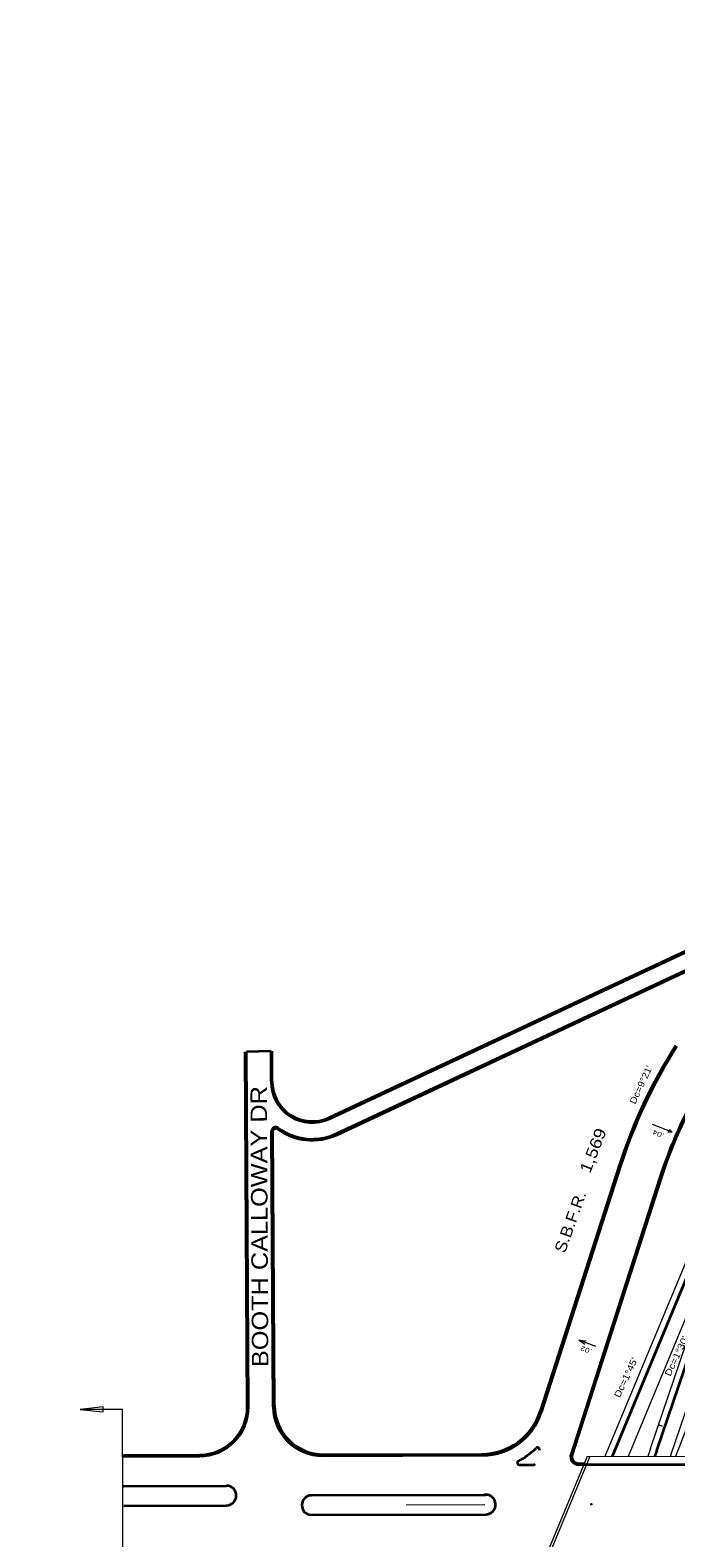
# Model space of a CAD drawing. Extents: x 2354993 to 2372084, y 6966390 to 6990057.
# Drawn here: x 2364099 to 2364884, y 6980481 to 6982315 of the extents above; entities that cross this region are included whole.
import ezdxf
from ezdxf.enums import TextEntityAlignment as Align

# ---------------------------------------------------------------- set-up
doc = ezdxf.new("R2010")
doc.units = 0
doc.header["$LTSCALE"] = 3.2
doc.header["$PDMODE"] = 32
doc.header["$PDSIZE"] = 1.6
for name, color, linetype, lineweight in [('1', 7, 'Continuous', 13), ('13', 7, 'Continuous', 13), ('15', 7, 'Continuous', 13), ('17', 7, 'Continuous', 13), ('19', 7, 'Continuous', 13), ('2', 7, 'Continuous', 35), ('4', 7, 'Continuous', 13), ('5', 7, 'Continuous', 35), ('8', 7, 'Continuous', 13), ('9', 7, 'Continuous', 13)]:
    doc.layers.add(name, color=color, linetype=linetype, lineweight=lineweight)

msp = doc.modelspace()

# ---------------------------------------------------------------- linework, layer by layer
at = {"layer": '1'}
for q in [(2364856.139, 6980983.553), (2364874.732, 6980974.05), (2364876.587, 6980977.317)]:
    msp.add_line((2364879.743, 6980974.088), q, dxfattribs=at)
at = {"layer": '15'}
msp.add_lwpolyline([(2364212.059, 6980404.032), (2364211.303, 6980637.104), (2364159.893, 6980636.937), (2364187.903, 6980634.029), (2364187.883, 6980640.028), (2364159.893, 6980636.937)], dxfattribs=at)
at = {"layer": '19'}
for p, q in [((2364766.943, 6980721.165), (2364773.594, 6980716.189)), ((2364766.943, 6980721.165), (2364775.222, 6980720.439)), ((2364786.963, 6980713.517), (2364766.943, 6980721.165))]:
    msp.add_line(p, q, dxfattribs=at)
at = {"layer": '2'}
for p, q in [((2364391.894, 6981072.689), (2364362.145, 6981071.936)), ((2364995.931, 6981035.023), (2364806.866, 6980579.777)), ((2364861.207, 6980586.955), (2365010.841, 6981027.825)), ((2364815.569, 6980933.575), (2364719.53, 6980634.813)), ((2364816.997, 6980933.115), (2364720.623, 6980633.313)), ((2364864.598, 6980917.813), (2364756.875, 6980582.707)), ((2364866.026, 6980917.355), (2364757.927, 6980581.077)), ((2364766.423, 6980571.147), (2364773.035, 6980571.167)), ((2364766.428, 6980569.647), (2365268.294, 6980571.275))]:
    msp.add_line(p, q, dxfattribs=at)
at = {"layer": '2', "lineweight": 13}
msp.add_line((2364868.163, 6980616.404), (2364863.537, 6980618.306), dxfattribs=at)
at = {"layer": '2'}
for centre, radius, start, end in [((2365412.01, 6980741.844), 575, 137.55934, 162.17959), ((2365412.01, 6980741.844), 573.5, 137.55934, 162.17959), ((2365412.01, 6980741.844), 626.5, 147.37736, 162.17959), ((2365412.01, 6980741.844), 625, 147.37736, 162.17959), ((2364766.395, 6980579.646), 10, 162.1796, 270.18593), ((2364766.395, 6980579.646), 8.5, 162.1796, 270.18593), ((2370300.051, 6978740.971), 5743.578, 161.2524, 161.32623)]:
    msp.add_arc(centre, radius, start, end, dxfattribs=at)
at = {"layer": '4'}
for p, q in [((2364988.543, 6981038.091), (2364798.192, 6980579.749)), ((2364878.249, 6980581.158), (2365013.559, 6980979.825)), ((2364911.473, 6980784.729), (2364826.382, 6980579.841)), ((2364853.631, 6980589.527), (2364918.845, 6980781.667)), ((2364884.273, 6980580.029), (2364899.617, 6980619.817))]:
    msp.add_line(p, q, dxfattribs=at)
for centre, radius, start, end in [((2370300.051, 6978740.971), 5751.578, 161.2524, 161.35344), ((2370300.048, 6978740.957), 5725.578, 161.25239, 161.26454)]:
    msp.add_arc(centre, radius, start, end, dxfattribs=at)
at = {"layer": '5'}
for p, q in [((2364462.463, 6980991.963), (2365011.662, 6981248.793)), ((2364463.098, 6980990.605), (2365012.297, 6981247.435)), ((2364471.57, 6980972.489), (2364995.066, 6981217.297)), ((2364472.205, 6980971.129), (2364995.702, 6981215.939)), ((2364363.031, 6980640.465), (2364360.645, 6981071.95)), ((2364364.531, 6980640.473), (2364362.145, 6981071.936)), ((2364391.918, 6981035.865), (2364391.894, 6981072.689)), ((2364393.418, 6981035.867), (2364393.394, 6981072.689)), ((2364394.533, 6980640.301), (2364392.68, 6980975.305)), ((2364396.024, 6980641.812), (2364394.18, 6980975.315)), ((2364212.213, 6980579.839), (2364304.727, 6980580.141)), ((2364212.519, 6980581.341), (2364304.723, 6980581.641)), ((2364454.727, 6980580.633), (2364649.465, 6980581.266)), ((2364456.218, 6980582.144), (2364648.372, 6980582.766)), ((2364694.002, 6980569.411), (2364711.252, 6980569.466)), ((2364212.641, 6980543.847), (2364337.806, 6980544.253)), ((2364440.321, 6980532.586), (2364653.411, 6980533.278)), ((2364212.718, 6980519.849), (2364337.882, 6980520.255)), ((2364440.125, 6980508.585), (2364653.513, 6980509.278))]:
    msp.add_line(p, q, dxfattribs=at)
at = {"layer": '5', "lineweight": 13}
for p, q in [((2364776.569, 6980579.679), (2364728.333, 6980463.531)), ((2364779.822, 6980579.689), (2364731.586, 6980463.541)), ((2364776.569, 6980579.679), (2365273.39, 6980581.292)), ((2364766.425, 6980570.647), (2365268.291, 6980572.275))]:
    msp.add_line(p, q, dxfattribs=at)
at = {"layer": '5'}
for centre, radius, start, end in [((2364441.918, 6981035.898), 50, 180.03669, 295.06272), ((2364441.918, 6981035.898), 48.5, 180.03669, 295.06272), ((2364397.68, 6980975.334), 5, 53.85481, 180.31682), ((2364397.68, 6980975.333), 3.5, 53.85483, 180.31682), ((2364441.918, 6981035.898), 71.5, 233.85483, 295.06321), ((2364441.918, 6981035.898), 70, 233.85481, 295.06292), ((2364304.532, 6980640.141), 58.5, 270.18698, 0.31682), ((2364304.532, 6980640.141), 60, 270.18697, 0.31682), ((2364454.532, 6980640.633), 60, 180.31685, 270.18617), ((2364456.023, 6980642.143), 60, 180.31686, 270.18557), ((2364648.129, 6980657.766), 75, 270.1855, 342.17971), ((2364649.222, 6980656.265), 75, 270.18614, 342.1796), ((2364649.222, 6980656.265), 93, 297.95774, 314.40722), ((2364716.048, 6980588.042), 2.5, 342.18249, 134.40722), ((2364693.994, 6980571.911), 2.5, 117.95774, 270.18545), ((2364711.246, 6980571.466), 2, 270.18405, 342.18207), ((2364337.694, 6980532.254), 12, 270.89854, 89.46436), ((2364441.434, 6980520.513), 12, 94.01279, 263.73872), ((2364653.272, 6980521.276), 12, 271.15204, 102.25782)]:
    msp.add_arc(centre, radius, start, end, dxfattribs=at)
at = {"layer": '8'}
msp.add_line((2364556.228, 6980520.961), (2364652.074, 6980521.273), dxfattribs=at)
at = {"layer": '9'}
msp.add_arc((2360722.521, 6984327.136), 5729.573, 359.50797, 359.50797, dxfattribs=at)
msp.add_point((2364781.691, 6980521.694), dxfattribs=at)

# ---------------------------------------------------------------- texts
at = {"layer": '13', "width": 1.15}
msp.add_text('BOOTH CALLOWAY DR', height=20, rotation=90.317, dxfattribs=at).set_placement((2364387.791, 6980859.464), align=Align.CENTER)
at = {"layer": '13'}
for s, rotation, width, p in [('1,569', 68.675, 1.2, (2364779.967, 6980923.233)), ('S.B.F.R.', 70.193, 1.1, (2364749.474, 6980826.321))]:
    msp.add_text(s, height=14, rotation=rotation, dxfattribs=dict(at, width=width)).set_placement(p)
at = {"layer": '17'}
for s, width, p in [("Dc=9°21'", 1.15, (2364834.884, 6981007.588)), ("Dc=1°30'", 1.2, (2364877.588, 6980676.573)), ("Dc=1°45'", 1.2, (2364816.082, 6980650.481))]:
    msp.add_text(s, height=8, rotation=64.778, dxfattribs=dict(at, width=width)).set_placement(p)
at = {"layer": '19'}
for s, height, rotation, width, p in [('.04', 5.999, 156.308, 1.3, (2364871.003, 6980971.987)), ('.02', 6, 159.133, 1.25, (2364782.821, 6980709.764))]:
    msp.add_text(s, height=height, rotation=rotation, dxfattribs=dict(at, width=width)).set_placement(p)

doc.saveas('drawing.dxf')
